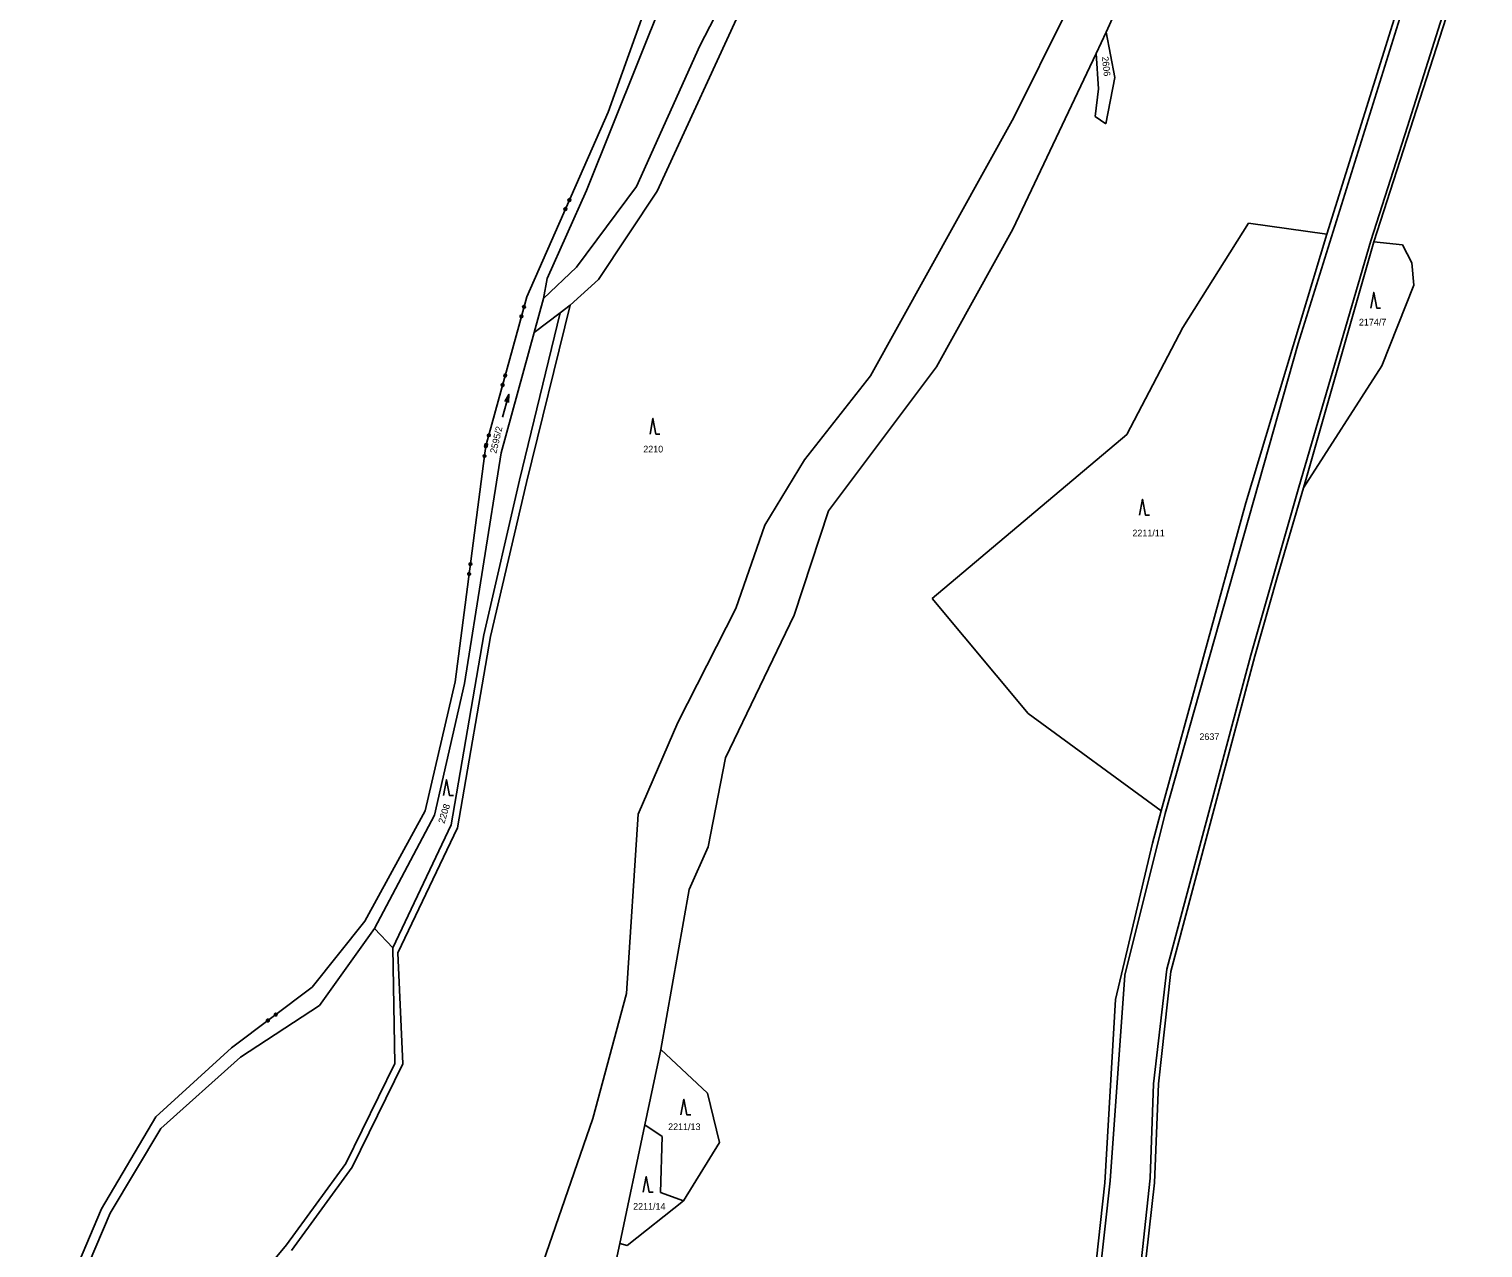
# Model space of a CAD drawing. Extents: x -806774 to -803680, y -1151731 to -1150053.
# Drawn here: x -806756.2 to -806387.2, y -1151434 to -1151124.5 of the extents above; entities that cross this region are included whole.
import ezdxf

# ---------------------------------------------------------------- set-up
doc = ezdxf.new("R2010")
doc.units = 0
for name, color, linetype in [('1', 7, 'Continuous'), ('2', 7, 'Continuous'), ('3', 7, 'Continuous'), ('4', 7, 'Continuous')]:
    doc.layers.add(name, color=color, linetype=linetype)

msp = doc.modelspace()

# ---------------------------------------------------------------- linework, layer by layer
at = {"layer": '1'}
for p, q in [((-806482.86, -1151125.33), (-806462.86, -1151081.06)), ((-806426.85, -1151176.65), (-806399.13, -1151087.92)), ((-806414.88, -1151178.55), (-806387.22, -1151092.44)), ((-806614.73, -1151165.53), (-806590.53, -1151105.18)), ((-806594.42, -1151104.37), (-806609.22, -1151145.61)), ((-806596.74, -1151165.66), (-806574.21, -1151116.5)), ((-806578.53, -1151114.39), (-806585.93, -1151128.77)), ((-806493.12, -1151120.59), (-806506.25, -1151146.99)), ((-806485.36, -1151130.76), (-806482.86, -1151125.33)), ((-806480.64, -1151136.87), (-806482.86, -1151125.33)), ((-806585.93, -1151128.77), (-806602.05, -1151164.55)), ((-806506.53, -1151175.36), (-806485.36, -1151130.76)), ((-806485.36, -1151130.76), (-806484.75, -1151139.73)), ((-806482.92, -1151148.56), (-806480.64, -1151136.87)), ((-806484.75, -1151139.73), (-806485.62, -1151146.7)), ((-806609.22, -1151145.61), (-806629.85, -1151192.49)), ((-806506.25, -1151146.99), (-806542.64, -1151212.58)), ((-806485.62, -1151146.7), (-806482.92, -1151148.56)), ((-806602.05, -1151164.55), (-806617.26, -1151184.97)), ((-806624.64, -1151187.9), (-806614.73, -1151165.53)), ((-806611.66, -1151188.15), (-806596.74, -1151165.66)), ((-806525.91, -1151210.3), (-806506.53, -1151175.36)), ((-806446.68, -1151173.85), (-806463.36, -1151200.29)), ((-806426.85, -1151176.65), (-806446.68, -1151173.85)), ((-806447.38, -1151244.82), (-806426.85, -1151176.65)), ((-806432.32, -1151239.57), (-806414.88, -1151178.55)), ((-806414.88, -1151178.55), (-806407.59, -1151179.35)), ((-806407.59, -1151179.35), (-806405.25, -1151183.88)), ((-806617.26, -1151184.97), (-806625.62, -1151192.98)), ((-806405.25, -1151183.88), (-806404.72, -1151189.55)), ((-806625.62, -1151192.98), (-806624.64, -1151187.9)), ((-806618.82, -1151194.62), (-806611.66, -1151188.15)), ((-806404.72, -1151189.55), (-806412.88, -1151210.03)), ((-806629.85, -1151192.49), (-806631.9, -1151199.99)), ((-806627.97, -1151201.54), (-806625.62, -1151192.98)), ((-806621.39, -1151196.55), (-806631.7, -1151239.08)), ((-806629.95, -1151239.62), (-806618.82, -1151194.62)), ((-806621.39, -1151196.55), (-806627.97, -1151201.54)), ((-806618.82, -1151194.62), (-806621.39, -1151196.55)), ((-806631.9, -1151199.99), (-806639.39, -1151227.32)), ((-806636.35, -1151232.1), (-806627.97, -1151201.54)), ((-806463.36, -1151200.29), (-806477.54, -1151227.46)), ((-806542.64, -1151212.58), (-806559.38, -1151233.91)), ((-806553.28, -1151246.87), (-806525.91, -1151210.3)), ((-806412.88, -1151210.03), (-806432.75, -1151241.03)), ((-806639.39, -1151227.32), (-806640.21, -1151230.33)), ((-806477.54, -1151227.46), (-806526.98, -1151269.12)), ((-806640.21, -1151230.33), (-806640.55, -1151232.93)), ((-806640.55, -1151232.93), (-806648.05, -1151290.23)), ((-806645.65, -1151290.7), (-806636.35, -1151232.1)), ((-806559.38, -1151233.91), (-806569.42, -1151250.48)), ((-806631.7, -1151239.08), (-806640.72, -1151278.37)), ((-806639.08, -1151278.78), (-806629.95, -1151239.62)), ((-806439.41, -1151263.77), (-806432.75, -1151241.03)), ((-806432.75, -1151241.03), (-806432.32, -1151239.57)), ((-806468.83, -1151323), (-806447.38, -1151244.82)), ((-806561.98, -1151273.31), (-806553.28, -1151246.87)), ((-806569.42, -1151250.48), (-806576.79, -1151271.69)), ((-806445.1, -1151283.71), (-806439.41, -1151263.77)), ((-806576.79, -1151271.69), (-806591.51, -1151300.57)), ((-806526.98, -1151269.12), (-806502.64, -1151298.29)), ((-806579.39, -1151309.52), (-806561.98, -1151273.31)), ((-806640.72, -1151278.37), (-806649.07, -1151326.59)), ((-806647.47, -1151327.32), (-806639.08, -1151278.78)), ((-806466.41, -1151363.84), (-806445.1, -1151283.71)), ((-806648.05, -1151290.23), (-806655.64, -1151323.05)), ((-806653.24, -1151324.08), (-806645.65, -1151290.7)), ((-806591.51, -1151300.57), (-806601.55, -1151323.84)), ((-806502.64, -1151298.29), (-806468.83, -1151323)), ((-806583.8, -1151332.16), (-806579.39, -1151309.52)), ((-806655.64, -1151323.05), (-806670.93, -1151351.06)), ((-806471.09, -1151331.22), (-806468.83, -1151323)), ((-806668.53, -1151352.86), (-806653.24, -1151324.08)), ((-806649.07, -1151326.59), (-806663.87, -1151357.76)), ((-806601.55, -1151323.84), (-806604.52, -1151369.36)), ((-806662.6, -1151359.05), (-806647.47, -1151327.32)), ((-806588.67, -1151342.95), (-806583.8, -1151332.16)), ((-806480.46, -1151370.89), (-806471.09, -1151331.22)), ((-806595.8, -1151383.59), (-806588.67, -1151342.95)), ((-806670.93, -1151351.06), (-806684.29, -1151367.82)), ((-806682.49, -1151372.42), (-806668.53, -1151352.86)), ((-806668.53, -1151352.86), (-806663.87, -1151357.76)), ((-806663.87, -1151357.76), (-806663.36, -1151387.16)), ((-806661.31, -1151387.23), (-806662.6, -1151359.05)), ((-806469.56, -1151392.34), (-806466.41, -1151363.84)), ((-806684.29, -1151367.82), (-806704.75, -1151383.15)), ((-806604.52, -1151369.36), (-806613.09, -1151401.09)), ((-806483.18, -1151417.5), (-806480.46, -1151370.89)), ((-806702.51, -1151385.53), (-806682.49, -1151372.42)), ((-806704.75, -1151383.15), (-806723.98, -1151400.7)), ((-806722.68, -1151403.66), (-806702.51, -1151385.53)), ((-806599.86, -1151402.77), (-806595.8, -1151383.59)), ((-806595.8, -1151383.59), (-806584.01, -1151394.69)), ((-806663.36, -1151387.16), (-806675.8, -1151412.56)), ((-806674.18, -1151413.49), (-806661.31, -1151387.23)), ((-806470.53, -1151417.49), (-806469.56, -1151392.34)), ((-806584.01, -1151394.69), (-806580.97, -1151407.19)), ((-806723.98, -1151400.7), (-806737.78, -1151424.04)), ((-806735.55, -1151425.13), (-806722.68, -1151403.66)), ((-806613.09, -1151401.09), (-806631.37, -1151454.08)), ((-806606.24, -1151432.86), (-806599.86, -1151402.77)), ((-806599.86, -1151402.77), (-806595.52, -1151405.73)), ((-806595.52, -1151405.73), (-806595.89, -1151419.89)), ((-806580.97, -1151407.19), (-806590.12, -1151421.99)), ((-806675.8, -1151412.56), (-806690.86, -1151433.2)), ((-806689.56, -1151434.62), (-806674.18, -1151413.49)), ((-806488.73, -1151468.39), (-806483.18, -1151417.5)), ((-806476.69, -1151471.9), (-806470.53, -1151417.49)), ((-806590.12, -1151421.99), (-806604.4, -1151433.36)), ((-806595.89, -1151419.89), (-806590.12, -1151421.99)), ((-806737.78, -1151424.04), (-806756.15, -1151467.4)), ((-806752.59, -1151465.18), (-806735.55, -1151425.13)), ((-806690.86, -1151433.2), (-806706.27, -1151451.72)), ((-806611.33, -1151456.55), (-806606.24, -1151432.86)), ((-806604.4, -1151433.36), (-806606.24, -1151432.86))]:
    msp.add_line(p, q, dxfattribs=at)
for points in [[(-806618.81, -1151168.2), (-806619.06, -1151168.3), (-806619.31, -1151168.19), (-806619.41, -1151167.94), (-806619.3, -1151167.69), (-806619.05, -1151167.59), (-806618.8, -1151167.7), (-806618.7, -1151167.95), (-806618.81, -1151168.2), (-806618.84, -1151168.17), (-806618.75, -1151167.95), (-806618.79, -1151167.85), (-806618.95, -1151168.22), (-806619.05, -1151168.26), (-806618.83, -1151167.74), (-806618.9, -1151167.71), (-806619.13, -1151168.22), (-806619.2, -1151168.19), (-806618.98, -1151167.68), (-806619.05, -1151167.65), (-806619.27, -1151168.16), (-806619.32, -1151168.05), (-806619.15, -1151167.69), (-806619.26, -1151167.73), (-806619.36, -1151167.95)], [(-806619.82, -1151170.49), (-806620.07, -1151170.59), (-806620.32, -1151170.48), (-806620.41, -1151170.23), (-806620.3, -1151169.98), (-806620.05, -1151169.88), (-806619.81, -1151169.99), (-806619.71, -1151170.24), (-806619.82, -1151170.49), (-806619.84, -1151170.44), (-806619.75, -1151170.22), (-806619.79, -1151170.12), (-806619.95, -1151170.49), (-806620.05, -1151170.53), (-806619.83, -1151170.01), (-806619.9, -1151169.98), (-806620.13, -1151170.49), (-806620.2, -1151170.46), (-806619.97, -1151169.95), (-806620.05, -1151169.92), (-806620.27, -1151170.43), (-806620.31, -1151170.32), (-806620.15, -1151169.96), (-806620.26, -1151170), (-806620.35, -1151170.22)], [(-806630.94, -1151197.7), (-806631.18, -1151197.84), (-806631.44, -1151197.77), (-806631.57, -1151197.53), (-806631.5, -1151197.27), (-806631.27, -1151197.14), (-806631, -1151197.21), (-806630.87, -1151197.44), (-806630.94, -1151197.7), (-806630.97, -1151197.66), (-806630.91, -1151197.43), (-806630.97, -1151197.33), (-806631.07, -1151197.72), (-806631.17, -1151197.78), (-806631.02, -1151197.24), (-806631.1, -1151197.22), (-806631.25, -1151197.76), (-806631.32, -1151197.73), (-806631.18, -1151197.19), (-806631.25, -1151197.17), (-806631.4, -1151197.71), (-806631.46, -1151197.62), (-806631.35, -1151197.23), (-806631.45, -1151197.29), (-806631.51, -1151197.52)], [(-806630.28, -1151195.29), (-806630.52, -1151195.43), (-806630.78, -1151195.35), (-806630.91, -1151195.12), (-806630.84, -1151194.86), (-806630.61, -1151194.73), (-806630.35, -1151194.8), (-806630.21, -1151195.03), (-806630.28, -1151195.29), (-806630.32, -1151195.27), (-806630.26, -1151195.04), (-806630.31, -1151194.94), (-806630.42, -1151195.33), (-806630.52, -1151195.38), (-806630.37, -1151194.84), (-806630.45, -1151194.82), (-806630.59, -1151195.36), (-806630.67, -1151195.34), (-806630.52, -1151194.8), (-806630.6, -1151194.78), (-806630.75, -1151195.32), (-806630.8, -1151195.22), (-806630.7, -1151194.84), (-806630.8, -1151194.89), (-806630.86, -1151195.12)], [(-806635.05, -1151212.71), (-806635.29, -1151212.84), (-806635.55, -1151212.77), (-806635.68, -1151212.54), (-806635.61, -1151212.28), (-806635.38, -1151212.14), (-806635.12, -1151212.21), (-806634.98, -1151212.45), (-806635.05, -1151212.71), (-806635.09, -1151212.69), (-806635.03, -1151212.46), (-806635.08, -1151212.36), (-806635.19, -1151212.74), (-806635.29, -1151212.8), (-806635.14, -1151212.26), (-806635.22, -1151212.24), (-806635.36, -1151212.78), (-806635.44, -1151212.76), (-806635.29, -1151212.22), (-806635.37, -1151212.2), (-806635.52, -1151212.74), (-806635.57, -1151212.64), (-806635.47, -1151212.25), (-806635.57, -1151212.31), (-806635.63, -1151212.54)], [(-806635.71, -1151215.12), (-806635.95, -1151215.25), (-806636.21, -1151215.18), (-806636.34, -1151214.95), (-806636.27, -1151214.69), (-806636.04, -1151214.55), (-806635.78, -1151214.62), (-806635.64, -1151214.86), (-806635.71, -1151215.12), (-806635.74, -1151215.08), (-806635.68, -1151214.85), (-806635.74, -1151214.75), (-806635.84, -1151215.14), (-806635.94, -1151215.19), (-806635.79, -1151214.65), (-806635.87, -1151214.63), (-806636.02, -1151215.17), (-806636.1, -1151215.15), (-806635.95, -1151214.61), (-806636.02, -1151214.59), (-806636.17, -1151215.13), (-806636.23, -1151215.03), (-806636.12, -1151214.64), (-806636.22, -1151214.7), (-806636.28, -1151214.93)], [(-806639.21, -1151227.88), (-806639.44, -1151228.01), (-806639.7, -1151227.94), (-806639.84, -1151227.71), (-806639.77, -1151227.45), (-806639.53, -1151227.31), (-806639.27, -1151227.38), (-806639.14, -1151227.62), (-806639.21, -1151227.88), (-806639.25, -1151227.86), (-806639.18, -1151227.63), (-806639.24, -1151227.53), (-806639.34, -1151227.91), (-806639.44, -1151227.97), (-806639.29, -1151227.43), (-806639.37, -1151227.41), (-806639.52, -1151227.95), (-806639.6, -1151227.93), (-806639.45, -1151227.39), (-806639.53, -1151227.37), (-806639.67, -1151227.91), (-806639.73, -1151227.81), (-806639.62, -1151227.42), (-806639.72, -1151227.48), (-806639.79, -1151227.71)], [(-806639.92, -1151230.61), (-806640.14, -1151230.77), (-806640.4, -1151230.74), (-806640.57, -1151230.53), (-806640.53, -1151230.26), (-806640.32, -1151230.09), (-806640.05, -1151230.13), (-806639.89, -1151230.34), (-806639.92, -1151230.61), (-806639.96, -1151230.6), (-806639.93, -1151230.36), (-806640, -1151230.27), (-806640.05, -1151230.66), (-806640.14, -1151230.73), (-806640.07, -1151230.18), (-806640.15, -1151230.17), (-806640.22, -1151230.72), (-806640.3, -1151230.71), (-806640.23, -1151230.16), (-806640.31, -1151230.15), (-806640.38, -1151230.7), (-806640.45, -1151230.61), (-806640.4, -1151230.22), (-806640.49, -1151230.28), (-806640.52, -1151230.52)], [(-806639.87, -1151230.29), (-806640.1, -1151230.42), (-806640.36, -1151230.35), (-806640.49, -1151230.12), (-806640.42, -1151229.86), (-806640.19, -1151229.72), (-806639.93, -1151229.8), (-806639.8, -1151230.03), (-806639.87, -1151230.29), (-806639.9, -1151230.25), (-806639.84, -1151230.02), (-806639.89, -1151229.92), (-806640, -1151230.31), (-806640.09, -1151230.36), (-806639.95, -1151229.82), (-806640.02, -1151229.8), (-806640.17, -1151230.34), (-806640.25, -1151230.32), (-806640.1, -1151229.78), (-806640.18, -1151229.76), (-806640.33, -1151230.3), (-806640.38, -1151230.2), (-806640.28, -1151229.81), (-806640.38, -1151229.87), (-806640.44, -1151230.1)], [(-806640.25, -1151233.09), (-806640.46, -1151233.25), (-806640.73, -1151233.22), (-806640.89, -1151233), (-806640.86, -1151232.74), (-806640.64, -1151232.57), (-806640.38, -1151232.61), (-806640.21, -1151232.82), (-806640.25, -1151233.09), (-806640.28, -1151233.05), (-806640.25, -1151232.82), (-806640.32, -1151232.73), (-806640.37, -1151233.12), (-806640.46, -1151233.19), (-806640.39, -1151232.64), (-806640.47, -1151232.63), (-806640.54, -1151233.18), (-806640.62, -1151233.17), (-806640.55, -1151232.62), (-806640.63, -1151232.61), (-806640.7, -1151233.16), (-806640.77, -1151233.07), (-806640.72, -1151232.67), (-806640.81, -1151232.74), (-806640.84, -1151232.98)], [(-806643.84, -1151260.56), (-806644.06, -1151260.72), (-806644.32, -1151260.69), (-806644.49, -1151260.48), (-806644.45, -1151260.21), (-806644.24, -1151260.04), (-806643.97, -1151260.08), (-806643.81, -1151260.29), (-806643.84, -1151260.56), (-806643.88, -1151260.55), (-806643.85, -1151260.31), (-806643.92, -1151260.22), (-806643.97, -1151260.61), (-806644.06, -1151260.68), (-806643.99, -1151260.13), (-806644.07, -1151260.12), (-806644.14, -1151260.67), (-806644.22, -1151260.66), (-806644.15, -1151260.11), (-806644.23, -1151260.1), (-806644.3, -1151260.65), (-806644.37, -1151260.56), (-806644.32, -1151260.17), (-806644.41, -1151260.23), (-806644.44, -1151260.47)], [(-806644.17, -1151263.04), (-806644.38, -1151263.2), (-806644.65, -1151263.17), (-806644.81, -1151262.95), (-806644.78, -1151262.69), (-806644.56, -1151262.52), (-806644.3, -1151262.56), (-806644.13, -1151262.77), (-806644.17, -1151263.04), (-806644.2, -1151263), (-806644.17, -1151262.77), (-806644.24, -1151262.68), (-806644.29, -1151263.07), (-806644.38, -1151263.14), (-806644.31, -1151262.59), (-806644.39, -1151262.58), (-806644.46, -1151263.13), (-806644.54, -1151263.12), (-806644.47, -1151262.57), (-806644.55, -1151262.56), (-806644.62, -1151263.11), (-806644.69, -1151263.02), (-806644.64, -1151262.62), (-806644.73, -1151262.69), (-806644.76, -1151262.93)], [(-806693.47, -1151375.1), (-806693.74, -1151375.06), (-806693.9, -1151374.85), (-806693.86, -1151374.58), (-806693.65, -1151374.42), (-806693.38, -1151374.46), (-806693.22, -1151374.67), (-806693.26, -1151374.94), (-806693.47, -1151375.1), (-806693.49, -1151375.06), (-806693.3, -1151374.92), (-806693.28, -1151374.81), (-806693.6, -1151375.05), (-806693.71, -1151375.03), (-806693.26, -1151374.69), (-806693.31, -1151374.63), (-806693.76, -1151374.97), (-806693.81, -1151374.9), (-806693.36, -1151374.57), (-806693.41, -1151374.5), (-806693.86, -1151374.84), (-806693.84, -1151374.73), (-806693.52, -1151374.49), (-806693.63, -1151374.47), (-806693.82, -1151374.61)], [(-806695.47, -1151376.6), (-806695.74, -1151376.56), (-806695.9, -1151376.34), (-806695.86, -1151376.08), (-806695.65, -1151375.92), (-806695.38, -1151375.95), (-806695.22, -1151376.17), (-806695.26, -1151376.44), (-806695.47, -1151376.6), (-806695.47, -1151376.55), (-806695.28, -1151376.4), (-806695.26, -1151376.29), (-806695.58, -1151376.53), (-806695.7, -1151376.52), (-806695.25, -1151376.18), (-806695.3, -1151376.12), (-806695.74, -1151376.45), (-806695.79, -1151376.39), (-806695.34, -1151376.05), (-806695.39, -1151375.99), (-806695.84, -1151376.32), (-806695.82, -1151376.21), (-806695.5, -1151375.97), (-806695.62, -1151375.96), (-806695.81, -1151376.1)]]:
    msp.add_lwpolyline(points, dxfattribs=at)
at = {"layer": '3'}
msp.add_line((-806636.04, -1151223.04), (-806634.38, -1151217.28), dxfattribs=at)
for points in [[(-806415.67, -1151195.39), (-806414.92, -1151191.39), (-806414.17, -1151195.39), (-806413.17, -1151195.39)], [(-806635.41, -1151219.06), (-806634.38, -1151217.28), (-806634.45, -1151219.34)], [(-806598.58, -1151227.37), (-806597.83, -1151223.37), (-806597.08, -1151227.37), (-806596.08, -1151227.37)], [(-806474.36, -1151247.92), (-806473.61, -1151243.92), (-806472.86, -1151247.92), (-806471.86, -1151247.92)], [(-806650.98, -1151319.11), (-806650.23, -1151315.11), (-806649.48, -1151319.11), (-806648.48, -1151319.11)], [(-806590.73, -1151400.23), (-806589.98, -1151396.23), (-806589.23, -1151400.23), (-806588.23, -1151400.23)], [(-806600.28, -1151419.87), (-806599.53, -1151415.87), (-806598.78, -1151419.87), (-806597.78, -1151419.87)]]:
    msp.add_lwpolyline(points, dxfattribs=at)
at = {"layer": '4'}
for p, q in [((-806397.9, -1151088.41), (-806434.09, -1151204.41)), ((-806406.37, -1151149.26), (-806388.26, -1151091.88)), ((-806415.66, -1151178.27), (-806406.37, -1151149.26)), ((-806433.94, -1151240.84), (-806415.66, -1151178.27)), ((-806434.09, -1151204.41), (-806467.83, -1151323.67)), ((-806446.14, -1151283.47), (-806433.94, -1151240.84)), ((-806467.4, -1151363.22), (-806446.14, -1151283.47)), ((-806467.83, -1151323.67), (-806478.12, -1151364.73)), ((-806470.8, -1151392.36), (-806467.4, -1151363.22)), ((-806478.12, -1151364.73), (-806481.78, -1151416.95)), ((-806471.65, -1151416.28), (-806470.8, -1151392.36)), ((-806481.78, -1151416.95), (-806487.77, -1151470.37)), ((-806477.67, -1151471.72), (-806471.65, -1151416.28))]:
    msp.add_line(p, q, dxfattribs=at)

# ---------------------------------------------------------------- texts
at = {"layer": '2'}
for s, rotation, p in [('2606', 276.3948, (-806483.94, -1151131.58)), ('2595/2', 76.8909, (-806637.57, -1151232.4)), ('2208', 72.8802, (-806650.77, -1151326.39))]:
    msp.add_text(s, height=1.7, rotation=rotation, dxfattribs=at).set_placement(p)
for s, p in [('2174/7', (-806418.69, -1151199.8)), ('2210', (-806600.3, -1151232.03)), ('2211/11', (-806476.17, -1151253.34)), ('2637', (-806459.17, -1151305.05)), ('2211/13', (-806593.98, -1151404.07)), ('2211/14', (-806602.87, -1151424.29))]:
    msp.add_text(s, height=1.7, dxfattribs=at).set_placement(p)

doc.saveas('drawing.dxf')
